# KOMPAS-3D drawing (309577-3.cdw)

Referenced files: Экскизы.cdw
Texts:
  КГТУ 00.00.000 ЭС
  Экскизы сборочных  единиц абсорбционной колонны @2~1400
  Текст на чертеже
  Размерные надписи
  Шероховатость
  Линия-выноска #1
  Линия-выноска #2
  Линия-выноска #3
  Отклонения формы и база
  Заголовок таблицы
  Ячейка таблицы
  Стрелка вида
  Обозначение изменения
  Фигурная скобка
  Номер узла
  Марка координационной оси
  VRCB
  Выносная надпись
  Обозначение узла
  Марка/позиционное обозначение с линией-выноской
  Марка/позиционное обозначение на линии
  Марка/позиционное обозначение без линии-выноски
  <template><curves><curve offset="10.000000"><style id="0" type="0"/></curve><curve offset="0.000000"><style id="2" type="0"/></curve><curve offset="-10.000000"><style id="0" type="0"/></curve></curves><tips><begin type="0" param="50.000000"><style id="0" type="0"/></begin><end type="0" param="50.000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
  Технические требования
  1. При изготовлении, испытании и постановке сборочных единиц,
  должны выполняться требованя:
  2. Материал деталей:
  крышка, - сталь Х18Н10Т ГОСТ 5632-72
  тарелка - сталь Ст3 ГОСТ 380-71.
  3. Сварные соединения должны соответствовать требованиям
  ОСТ 26-01-82-77 "Сварка в химическом машиностроении".
  4. Сварные швы в объеме 100% контролировать рентгенопросвчиванием.
  5. Размеры для справок.
  Тарелка ТСН - III
  Крышка
  Экскизы сборочных
  единиц абсорбционной
  колонны  1400
  КГТУ 00.00.000 ЭС-
Dimensions and other numbers on the sheet: 7; 14; 45; 260; 980; 1400; 250; 270; 12 отв.*; 24; 20 отв.*; 27; 405; 355; 1710; 1560; 4; 1:10; 28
